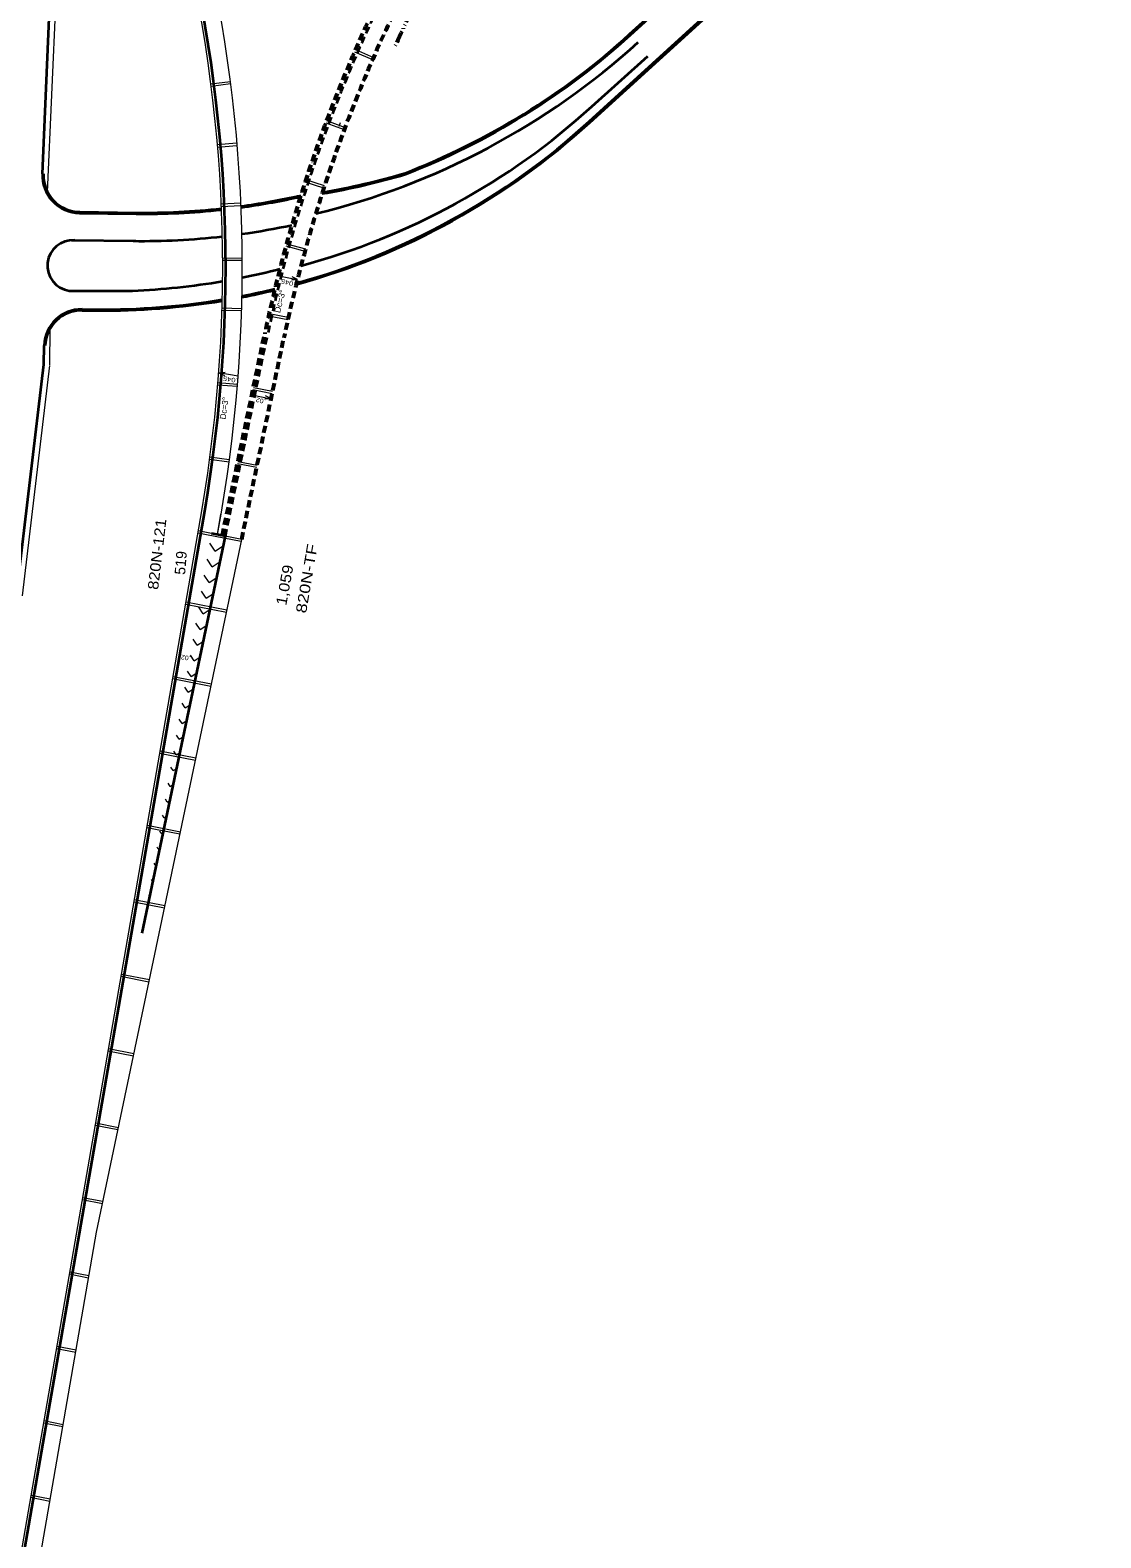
# Model space of a CAD drawing. Extents: x 2354993 to 2372084, y 6966390 to 6990057.
# Drawn here: x 2364667 to 2366085, y 6974745 to 6976742 of the extents above; entities that cross this region are included whole.
import ezdxf

# ---------------------------------------------------------------- set-up
doc = ezdxf.new("R2010")
doc.units = 0
doc.header["$LTSCALE"] = 3.2
doc.linetypes.add('DASH_DOUBLE_DOT', pattern=[9.2, 5, -1.2, 0.3, -1.2, 0.3, -1.2])
doc.linetypes.add('MEDIUM_DASHED', pattern=[4.5, 3, -1.5])
for name, color, linetype, lineweight in [('12', 7, 'Continuous', 13), ('13', 7, 'Continuous', 13), ('17', 7, 'Continuous', 13), ('19', 7, 'Continuous', 13), ('2', 7, 'Continuous', 35), ('4', 7, 'Continuous', 13), ('5', 7, 'Continuous', 35), ('60', 7, 'DASH_DOUBLE_DOT', 53), ('61', 7, 'Continuous', 13)]:
    doc.layers.add(name, color=color, linetype=linetype, lineweight=lineweight)

msp = doc.modelspace()

# ---------------------------------------------------------------- linework, layer by layer
at = {"layer": '12'}
for p, q in [((2365096.521, 6976713.391), (2365120.397, 6976703.098)), ((2365097.719, 6976716.141), (2365121.595, 6976705.847)), ((2364932.058, 6976673.71), (2364906.272, 6976670.388)), ((2364932.439, 6976670.735), (2364906.652, 6976667.414)), ((2365058.546, 6976619.394), (2365082.928, 6976610.363)), ((2365059.598, 6976622.202), (2365083.98, 6976613.172)), ((2365055.863, 6976532.894), (2365031.104, 6976540.83)), ((2365056.793, 6976535.746), (2365032.033, 6976543.683)), ((2365005.707, 6976456.21), (2365030.792, 6976449.371)), ((2365006.505, 6976459.1), (2365031.59, 6976452.262)), ((2364947.746, 6976439.942), (2364921.747, 6976439.789)), ((2364947.762, 6976436.943), (2364921.762, 6976436.79)), ((2364946.976, 6976373.133), (2364920.987, 6976373.885)), ((2364946.887, 6976370.135), (2364920.898, 6976370.888)), ((2365008.13, 6976358.355), (2364982.603, 6976363.334)), ((2365008.786, 6976361.284), (2364983.257, 6976366.263)), ((2364941.443, 6976272.877), (2364915.529, 6976274.989)), ((2364941.198, 6976269.888), (2364915.283, 6976271.999)), ((2364987.466, 6976260.5), (2364961.946, 6976265.478)), ((2364988.082, 6976263.437), (2364962.562, 6976268.415)), ((2364930.671, 6976173.053), (2364905.008, 6976176.492)), ((2364930.27, 6976170.081), (2364904.606, 6976173.52)), ((2364966.957, 6976162.616), (2364941.436, 6976167.593)), ((2364967.572, 6976165.553), (2364942.052, 6976170.53)), ((2364946.446, 6976064.731), (2364888.859, 6976075.962)), ((2364947.061, 6976067.668), (2364889.372, 6976078.919)), ((2364926.764, 6975970.796), (2364872.469, 6975981.384)), ((2364927.379, 6975973.733), (2364872.982, 6975984.341)), ((2364906.253, 6975872.912), (2364855.391, 6975882.83)), ((2364906.869, 6975875.849), (2364855.904, 6975885.787)), ((2364885.744, 6975775.027), (2364838.313, 6975784.277)), ((2364886.359, 6975777.964), (2364838.825, 6975787.232)), ((2364865.234, 6975677.145), (2364821.234, 6975685.724)), ((2364865.849, 6975680.081), (2364821.747, 6975688.681)), ((2364844.724, 6975579.26), (2364804.156, 6975587.171)), ((2364845.34, 6975582.197), (2364804.669, 6975590.128)), ((2364824.214, 6975481.376), (2364787.078, 6975488.619)), ((2364824.829, 6975484.312), (2364787.59, 6975491.573)), ((2364803.704, 6975383.491), (2364769.999, 6975390.064)), ((2364804.318, 6975386.428), (2364770.512, 6975393.02)), ((2364783.194, 6975285.607), (2364752.921, 6975291.511)), ((2364783.809, 6975288.544), (2364753.434, 6975294.468)), ((2364763.299, 6975190.66), (2364736.355, 6975195.914)), ((2364762.683, 6975187.724), (2364735.843, 6975192.958)), ((2364744.801, 6975092.383), (2364719.277, 6975097.36)), ((2364744.289, 6975089.427), (2364718.764, 6975094.404)), ((2364727.21, 6974990.872), (2364701.686, 6974995.85)), ((2364727.723, 6974993.831), (2364702.199, 6974998.809)), ((2364710.132, 6974892.321), (2364684.608, 6974897.298)), ((2364710.645, 6974895.277), (2364685.12, 6974900.253)), ((2364693.054, 6974793.767), (2364667.529, 6974798.744)), ((2364693.566, 6974796.725), (2364668.042, 6974801.701))]:
    msp.add_line(p, q, dxfattribs=at)
at = {"layer": '19'}
for p, q in [((2365021.106, 6976411.605), (2365012.825, 6976410.894)), ((2364916.883, 6976288.383), (2364925.161, 6976289.131)), ((2364986.024, 6976253.941), (2364977.743, 6976253.23))]:
    msp.add_line(p, q, dxfattribs=at)
for points in [[(2364995.797, 6976416.524), (2365021.106, 6976411.605), (2365013.699, 6976415.362)], [(2364942.214, 6976283.578), (2364916.883, 6976288.383), (2364924.307, 6976284.659)], [(2364960.715, 6976258.86), (2364986.024, 6976253.941), (2364978.617, 6976257.698)]]:
    msp.add_lwpolyline(points, dxfattribs=at)
at = {"layer": '2'}
msp.add_line((2364685.177, 6976299.01), (2364685.261, 6976324.55), dxfattribs=at)
at = {"layer": '4'}
msp.add_arc((2367020.832, 6975885.878), 2076.901, 159.32699, 159.47101, dxfattribs=at)
at = {"layer": '5'}
for p, q in [((2364683.134, 6976551.86), (2364717.405, 6977340.009)), ((2365461.706, 6976735.455), (2365523.82, 6976791.997)), ((2365407.189, 6976620.909), (2365556.136, 6976756.497)), ((2365408.199, 6976619.8), (2365557.146, 6976755.388)), ((2365410.613, 6976640.666), (2365484.741, 6976707.345)), ((2364684.633, 6976551.795), (2364683.134, 6976551.86)), ((2364732.47, 6976499.692), (2364807.291, 6976498.769)), ((2364732.489, 6976501.192), (2364807.31, 6976500.269)), ((2364721.568, 6976463.823), (2364806.847, 6976462.772)), ((2364718.768, 6976396.876), (2364802.345, 6976396.919)), ((2364735.68, 6976370.876), (2364755.262, 6976370.688)), ((2364735.694, 6976372.376), (2364755.276, 6976372.188)), ((2364686.76, 6976324.485), (2364685.261, 6976324.55)), ((2364648.854, 6975993.703), (2364685.177, 6976299.01)), ((2364592.006, 6974338.873), (2364898.046, 6976104.929)), ((2364925.467, 6976071.879), (2364907.042, 6976075.473)), ((2364815.346, 6975546.328), (2364925.467, 6976071.879))]:
    msp.add_line(p, q, dxfattribs=at)
at = {"layer": '5', "lineweight": 13}
for p, q in [((2364690.072, 6976527.283), (2364724.81, 6977326.163)), ((2364693.177, 6976298.984), (2364693.335, 6976346.84)), ((2364656.798, 6975992.758), (2364693.121, 6976298.065)), ((2364588.065, 6974339.557), (2364894.105, 6976105.613)), ((2364914.925, 6976074.108), (2364919.617, 6976101.182)), ((2364915.004, 6976073.933), (2364919.724, 6976101.173)), ((2364754.787, 6975150.037), (2364947.062, 6976067.668)), ((2364912.131, 6976052.127), (2364904.844, 6976062.789)), ((2364912.131, 6976052.127), (2364922.841, 6976059.346)), ((2364908.156, 6976031.357), (2364901.168, 6976041.581)), ((2364908.156, 6976031.357), (2364918.427, 6976038.279)), ((2364904.183, 6976010.591), (2364897.494, 6976020.377)), ((2364904.183, 6976010.591), (2364914.013, 6976017.217)), ((2364900.209, 6975989.825), (2364893.819, 6975999.173)), ((2364900.209, 6975989.825), (2364909.599, 6975996.153)), ((2364896.234, 6975969.053), (2364890.144, 6975977.963)), ((2364896.234, 6975969.053), (2364905.185, 6975975.086)), ((2364892.261, 6975948.288), (2364886.47, 6975956.761)), ((2364892.261, 6975948.288), (2364900.772, 6975954.024)), ((2364888.287, 6975927.519), (2364882.795, 6975935.553)), ((2364884.313, 6975906.753), (2364879.12, 6975914.349)), ((2364888.287, 6975927.519), (2364896.358, 6975932.96)), ((2364884.313, 6975906.753), (2364891.945, 6975911.897)), ((2364880.339, 6975885.984), (2364875.446, 6975893.143)), ((2364880.339, 6975885.984), (2364887.531, 6975890.832)), ((2364876.366, 6975865.217), (2364871.771, 6975871.938)), ((2364876.366, 6975865.217), (2364883.117, 6975869.767)), ((2364872.392, 6975844.451), (2364868.097, 6975850.735)), ((2364872.392, 6975844.451), (2364878.704, 6975848.705)), ((2364868.418, 6975823.684), (2364864.422, 6975829.53)), ((2364868.418, 6975823.684), (2364874.291, 6975827.641)), ((2364864.443, 6975802.913), (2364860.747, 6975808.321)), ((2364864.443, 6975802.913), (2364869.877, 6975806.575)), ((2364860.47, 6975782.147), (2364857.072, 6975787.118)), ((2364860.47, 6975782.147), (2364865.463, 6975785.513)), ((2364856.495, 6975761.375), (2364853.396, 6975765.908)), ((2364856.495, 6975761.375), (2364861.049, 6975764.445)), ((2364852.52, 6975740.604), (2364849.721, 6975744.699)), ((2364852.52, 6975740.604), (2364856.635, 6975743.379)), ((2364848.547, 6975719.835), (2364846.046, 6975723.492)), ((2364848.547, 6975719.835), (2364852.22, 6975722.312)), ((2364844.572, 6975699.066), (2364842.372, 6975702.285)), ((2364844.572, 6975699.066), (2364847.806, 6975701.246)), ((2364840.598, 6975678.295), (2364838.696, 6975681.077)), ((2364840.598, 6975678.295), (2364843.392, 6975680.179)), ((2364836.623, 6975657.525), (2364835.021, 6975659.869)), ((2364836.623, 6975657.525), (2364838.978, 6975659.113)), ((2364832.649, 6975636.755), (2364831.346, 6975638.661)), ((2364832.649, 6975636.755), (2364834.564, 6975638.047)), ((2364828.675, 6975615.989), (2364827.672, 6975617.456)), ((2364828.675, 6975615.989), (2364830.151, 6975616.983)), ((2364824.7, 6975595.216), (2364823.996, 6975596.246)), ((2364824.7, 6975595.216), (2364825.736, 6975595.914)), ((2364613.575, 6974335.122), (2364754.814, 6975150.165))]:
    msp.add_line(p, q, dxfattribs=at)
at = {"layer": '5', "linetype": 'MEDIUM_DASHED'}
msp.add_line((2364925.467, 6976071.879), (2364981.448, 6976339.048), dxfattribs=at)
at = {"layer": '5', "linetype": 'MEDIUM_DASHED', "lineweight": 53}
msp.add_line((2364947.062, 6976067.668), (2365002.98, 6976334.537), dxfattribs=at)
at = {"layer": '5'}
msp.add_lwpolyline([(2365460.696, 6976736.564), (2365522.81, 6976793.106), (2365788.855, 6977035.453)], dxfattribs=at)
at = {"layer": '5', "linetype": 'MEDIUM_DASHED', "lineweight": 53}
msp.add_lwpolyline([(2364921.553, 6976072.7), (2364977.534, 6976339.869), (2364977.533, 6976339.868)], dxfattribs=at)
for radius, start in [(1927.859, 114.19653), (1901.859, 114.19652)]:
    msp.add_arc((2366864.416, 6975944.503), radius, start, 168.16581, dxfattribs=at)
at = {"layer": '5', "linetype": 'MEDIUM_DASHED'}
msp.add_arc((2366864.416, 6975944.503), 1923.859, 114.19652, 168.16581, dxfattribs=at)
at = {"layer": '5', "lineweight": 13}
for radius in [1917.859, 1891.859]:
    msp.add_arc((2363030.028, 6976428.641), radius, 350.16881, 38.12295, dxfattribs=at)
at = {"layer": '5'}
for centre, radius, start, end in [((2363030.028, 6976428.641), 1895.859, 350.16881, 38.12295), ((2364818.89, 6977441.63), 953.43, 291.18831, 312.311), ((2364818.89, 6977441.63), 954.93, 291.18831, 312.311), ((2364813.366, 6977450.171), 978.93, 283.69992, 312.311), ((2364783.944, 6977329.083), 930.93, 285.04443, 312.3117), ((2364764.362, 6977327.074), 956.43, 285.45314, 312.3117), ((2364764.362, 6977327.074), 954.93, 285.50407, 312.3117), ((2364733.087, 6976549.688), 50, 177.51014, 269.29335), ((2364733.087, 6976549.688), 48.5, 177.51014, 269.29335), ((2364895.014, 6977455.068), 943, 279.67326, 286.57564), ((2364895.014, 6977455.068), 941.5, 279.72076, 286.57564), ((2364818.89, 6977441.63), 941.43, 277.76598, 282.30884), ((2364818.89, 6977441.63), 942.93, 277.75738, 282.30884), ((2364895.014, 6977455.068), 941.5, 277.61057, 277.95298), ((2364895.014, 6977455.068), 943, 277.61057, 277.90976), ((2364818.89, 6977441.63), 942.93, 269.29528, 276.17227), ((2364818.89, 6977441.63), 941.43, 269.29528, 276.17843), ((2364815.037, 6977405.676), 942.93, 278.06261, 282.15306), ((2364723.307, 6976430.218), 33.65, 85.61434, 262.24679), ((2364815.037, 6977405.676), 942.93, 269.29632, 276.47397), ((2364764.362, 6977327.074), 930.93, 281.35975, 284.51035), ((2364764.362, 6977327.074), 930.93, 272.3384, 279.72926), ((2364764.362, 6977327.074), 956.43, 281.03036, 283.68281), ((2364764.362, 6977327.074), 954.93, 281.04984, 283.72929), ((2364764.362, 6977327.074), 956.43, 269.45448, 279.44073), ((2364764.362, 6977327.074), 954.93, 269.45448, 279.45787), ((2364735.214, 6976322.378), 50, 89.44996, 177.51015), ((2364735.214, 6976322.378), 48.5, 89.44996, 177.51015)]:
    msp.add_arc(centre, radius, start, end, dxfattribs=at)
at = {"layer": '60'}
msp.add_arc((2366864.416, 6975944.503), 1881.859, 114.65077, 155.69784, dxfattribs=at)
at = {"layer": '61'}
for p, q in [((2364914.843, 6976590.548), (2364940.248, 6976592.683)), ((2364915.136, 6976587.06), (2364940.541, 6976589.195)), ((2364919.944, 6976512.037), (2364945.924, 6976513.135)), ((2364920.092, 6976508.54), (2364946.072, 6976509.638))]:
    msp.add_line(p, q, dxfattribs=at)

# ---------------------------------------------------------------- texts
at = {"layer": '13'}
for s, rotation, width, p in [('820N-121', 83.24, 1.15, (2364836.339, 6976000.314)), ('820N-TF', 80.363, 1.25, (2365032.358, 6975969.107)), ('1,059', 79.691, 1.15, (2365006.072, 6975979.488))]:
    msp.add_text(s, height=14, rotation=rotation, dxfattribs=dict(at, width=width)).set_placement(p)
msp.add_text('519', height=14, rotation=85.353, dxfattribs=at).set_placement((2364872.068, 6976020.364))
at = {"layer": '17', "width": 1.05}
msp.add_text('Dc=3°', height=8, rotation=75.446, dxfattribs=at).set_placement((2364997.721, 6976366.904))
at = {"layer": '17'}
msp.add_text('Dc=3°', height=8, rotation=82.162, dxfattribs=at).set_placement((2364925.831, 6976226.161))
at = {"layer": '19'}
for s, height, rotation, width, p in [('.045', 5.999, 165.77, 1.25, (2365018.815, 6976408.07)), ('.045', 6, 169.85, 1.25, (2364942.138, 6976280.612)), ('.02', 6, 165.493, 1.2, (2364979.429, 6976252.509)), ('.02', 6, 169.821, 1.15, (2364879.893, 6975912.726))]:
    msp.add_text(s, height=height, rotation=rotation, dxfattribs=dict(at, width=width)).set_placement(p)

doc.saveas('drawing.dxf')
